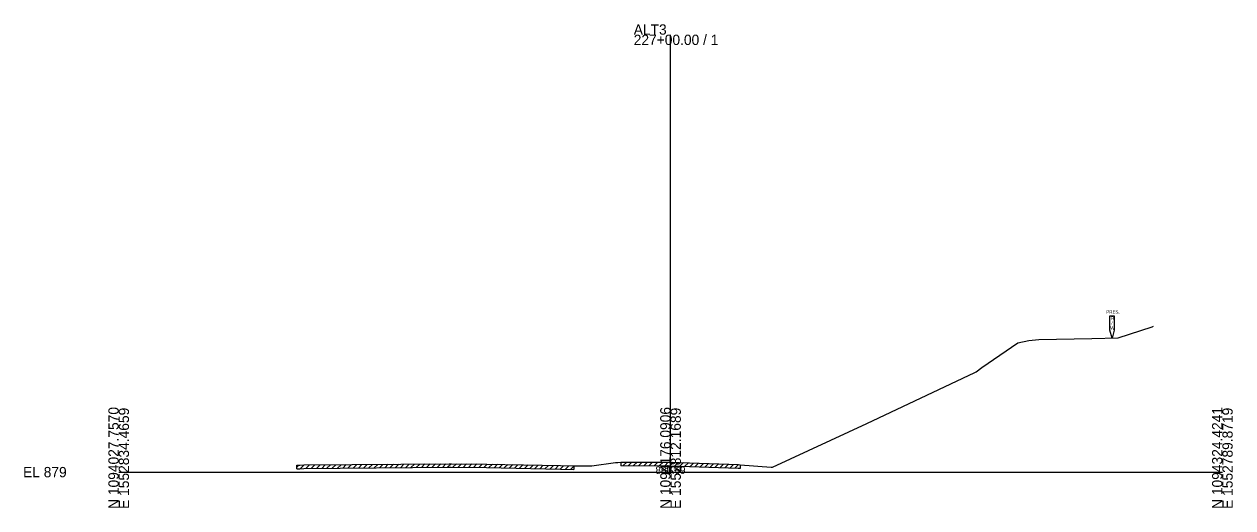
# Model space of a CAD drawing. Extents: x -26 to 1303, y -10 to 19582.
# Drawn here: x -25.7 to 302.8, y 490.3 to 621.6 of the extents above; entities that cross this region are included whole.
import ezdxf

# ---------------------------------------------------------------- set-up
doc = ezdxf.new("R2010")
doc.units = 0
for name, color, linetype in [('Default', 7, 'Continuous'), ('RD_GPK_XS_Cell', 7, 'Continuous'), ('RD_XS_ExGround', 7, 'Continuous'), ('RD_XS_ExPaveRet', 7, 'Continuous'), ('RD_XS_ExRW', 7, 'Continuous'), ('RD_XS_TX_Elev_EX', 7, 'Continuous')]:
    doc.layers.add(name, color=color, linetype=linetype)

msp = doc.modelspace()

# ---------------------------------------------------------------- linework, layer by layer
at = {"layer": 'RD_GPK_XS_Cell'}
for p, q in [((150, 500), (150, 618.8)), ((0, 500), (150, 500)), ((150, 500), (300, 500))]:
    msp.add_line(p, q, dxfattribs=at)
at = {"layer": 'RD_XS_ExGround'}
msp.add_lwpolyline([(48.42, 501.86), (49.26, 501.88), (50.32, 501.94), (89.8, 502.26), (90.42, 502.27), (99.96, 502.19), (120.1, 501.76), (123.68, 501.67), (128.57, 501.72), (135, 502.61), (135.71, 502.63), (136.45, 502.74), (148.79, 502.7), (149.84, 502.7), (168.43, 502.04), (168.89, 502.02), (177.34, 501.37), (177.72, 501.34), (203.38, 513.19), (232.68, 527.05), (233.09, 527.23), (234.64, 528.38), (244.42, 535.08), (247.43, 535.74), (250.09, 536.04), (264.48, 536.32), (271.63, 536.43), (280.95, 539.43), (281.3, 539.6)], dxfattribs=at)
at = {"layer": 'RD_XS_ExPaveRet'}
for p, q in [((136.45, 502.74), (136.45, 501.74)), ((136.45, 502.5), (136.68, 502.74)), ((137.15, 501.79), (138.09, 502.73)), ((138.56, 501.78), (139.5, 502.73)), ((139.97, 501.78), (140.91, 502.72)), ((141.38, 501.77), (142.32, 502.72)), ((142.79, 501.77), (143.73, 502.72)), ((144.2, 501.76), (145.14, 502.71)), ((145.61, 501.76), (146.55, 502.71)), ((147.02, 501.76), (147.96, 502.7)), ((148.43, 501.75), (149.37, 502.7)), ((149.83, 501.75), (150.75, 502.66)), ((48.43, 501.34), (48.97, 501.87)), ((48.43, 500.91), (48.43, 501.86)), ((49.45, 500.94), (50.44, 501.94)), ((50.91, 500.99), (51.87, 501.95)), ((52.34, 501), (53.3, 501.96)), ((53.76, 501.01), (54.72, 501.97)), ((55.19, 501.02), (56.15, 501.98)), ((56.62, 501.04), (57.57, 501.99)), ((58.04, 501.05), (59, 502.01)), ((59.47, 501.06), (60.43, 502.02)), ((60.89, 501.07), (61.85, 502.03)), ((62.32, 501.08), (63.28, 502.04)), ((63.75, 501.09), (64.7, 502.05)), ((65.17, 501.11), (66.13, 502.06)), ((66.6, 501.12), (67.56, 502.08)), ((68.02, 501.13), (68.98, 502.09)), ((69.45, 501.14), (70.41, 502.1)), ((70.88, 501.15), (71.83, 502.11)), ((72.3, 501.17), (73.26, 502.12)), ((73.73, 501.18), (74.69, 502.14)), ((75.15, 501.19), (76.11, 502.15)), ((76.58, 501.2), (77.54, 502.16)), ((78.01, 501.21), (78.96, 502.17)), ((79.43, 501.22), (80.39, 502.18)), ((80.86, 501.24), (81.82, 502.19)), ((82.28, 501.25), (83.24, 502.21)), ((83.71, 501.26), (84.67, 502.22)), ((85.14, 501.27), (86.09, 502.23)), ((86.56, 501.28), (87.52, 502.24)), ((87.99, 501.29), (88.95, 502.25)), ((89.41, 501.31), (90.38, 502.27)), ((90.84, 501.32), (91.78, 502.26)), ((92.24, 501.3), (93.18, 502.25)), ((93.64, 501.29), (94.58, 502.23)), ((95.04, 501.28), (95.99, 502.22)), ((96.45, 501.27), (97.39, 502.21)), ((97.85, 501.26), (98.79, 502.2)), ((99.25, 501.24), (100.19, 502.18)), ((100.64, 501.22), (101.57, 502.15)), ((102.03, 501.19), (102.96, 502.12)), ((103.41, 501.16), (104.34, 502.09)), ((104.8, 501.13), (105.73, 502.06)), ((106.18, 501.1), (107.11, 502.03)), ((107.57, 501.07), (108.5, 502)), ((108.95, 501.04), (109.88, 501.97)), ((110.33, 501.01), (111.26, 501.94)), ((111.72, 500.98), (112.65, 501.91)), ((113.1, 500.95), (114.03, 501.88)), ((114.49, 500.92), (115.42, 501.85)), ((115.87, 500.89), (116.8, 501.82)), ((117.26, 500.86), (118.19, 501.79)), ((118.64, 500.83), (119.57, 501.76)), ((120.03, 500.81), (120.95, 501.73)), ((121.41, 500.77), (122.34, 501.7)), ((122.79, 500.74), (123.68, 501.63)), ((123.68, 501.67), (123.68, 500.67)), ((151.2, 501.7), (152.12, 502.62)), ((152.57, 501.65), (153.48, 502.57)), ((153.93, 501.6), (154.85, 502.52)), ((155.3, 501.55), (156.22, 502.47)), ((156.66, 501.5), (157.58, 502.42)), ((158.03, 501.46), (158.95, 502.37)), ((159.4, 501.41), (160.31, 502.33)), ((160.76, 501.36), (161.68, 502.28)), ((162.13, 501.31), (163.05, 502.23)), ((163.49, 501.26), (164.41, 502.18)), ((164.86, 501.21), (165.78, 502.13)), ((166.23, 501.17), (167.14, 502.08)), ((167.59, 501.12), (168.51, 502.03)), ((168.9, 502.01), (168.9, 501.01))]:
    msp.add_line(p, q, dxfattribs=at)
for points in [[(48.43, 500.91), (49.28, 500.93), (50.36, 500.98), (89.74, 501.31), (90.37, 501.32), (99.96, 501.24), (120.07, 500.8), (123.68, 500.72)], [(136.45, 501.79), (136.45, 501.79), (148.78, 501.75), (149.84, 501.75), (168.41, 501.09), (168.9, 501.06)]]:
    msp.add_lwpolyline(points, dxfattribs=at)
at = {"layer": 'RD_XS_ExRW'}
msp.add_lwpolyline([(269.45, 542.42), (270.55, 542.42), (270.55, 538.59), (270, 536.41), (269.45, 538.59)], close=True, dxfattribs=at)

# ---------------------------------------------------------------- texts
at = {"layer": 'Default'}
msp.add_text('-', height=0.0001, dxfattribs=at).set_placement((0, 500))
at = {"layer": 'RD_GPK_XS_Cell'}
for s, p in [('ALT3', (140, 618.8)), ('227+00.00 / 1', (140, 616)), ('EL 879', (-26, 498.6))]:
    msp.add_text(s, height=2.8, dxfattribs=at).set_placement(p)
for s, p in [('N 1094027.7570', (0, 490)), ('E 1552834.4659', (2.8, 490)), ('N 1094176.0906', (150, 490)), ('E 1552812.1689', (152.8, 490)), ('N 1094324.4241', (300, 490)), ('E 1552789.8719', (302.8, 490))]:
    msp.add_text(s, height=2.8, rotation=90, dxfattribs=at).set_placement(p)
at = {"layer": 'RD_XS_ExRW'}
for s, p in [('PRES.', (268.45, 543.05)), ('R', (269.71, 541.33)), ('W', (269.53, 538.71)), ('/', (269.83, 540.02))]:
    msp.add_text(s, height=0.875, dxfattribs=at).set_placement(p)
at = {"layer": 'RD_XS_TX_Elev_EX'}
for height, p in [(2, (145.9, 499.52)), (1.25, (147.44, 500.27))]:
    msp.add_text('881.69', height=height, dxfattribs=at).set_placement(p)

doc.saveas('drawing.dxf')
